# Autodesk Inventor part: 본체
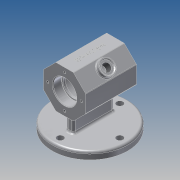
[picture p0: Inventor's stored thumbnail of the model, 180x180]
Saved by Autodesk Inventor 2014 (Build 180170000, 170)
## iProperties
Created: 2021-02
Part Number: 본체
Material: 알루미늄 6061
Document SubType Name: Modeling
Designer: kb542-20
Density: 2.71 g/cm^3
Appearance: 알루미늄 - 평지
Mass: 558.806 g
Surface Area: 509.67 cm^2
Volume: 206.202 cm^3
Author: kb542-20
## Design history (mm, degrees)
sketch "스케치1" dims "d0" = 58
  geometry: L1 (12.012, 29)-(29, 12.012); L2 (29, 12.012)-(29, -12.012); L3 (29, -12.012)-(12.012, -29); L4 (12.012, -29)-(-12.012, -29); L5 (-12.012, -29)-(-29, -12.012); L6 (-29, -12.012)-(-29, 12.012); L7 (-29, 12.012)-(-12.012, 29); L8 (-12.012, 29)-(12.012, 29); 5 further points
  constraints: 16 end point, 3 coincident, 1 horizontal, 1 midpoint, 1 vertical alignment, 19 other
extrude "돌출1" new body sketch "스케치1" stored distance "d1" = 70; taper "d2" = 0 deg
node "작업 평면1"
sketch "스케치3"
  geometry: C1 r 52 at (0, 0); C2 r 4.5 at (0, 41); C3 r 4.5 at (-41, 0); C4 r 4.5 at (0, -41); C5 r 4.5 at (41, 0); A1 r 41 centre (0, 0) between (0, 41) and (-41, 0); 1 further point
  constraints: 6 centre point, 4 point on circle, 3 equal radius, 2 coincident, 2 horizontal alignment, 2 vertical alignment
  dimensions: "d14" = 104 diameter of C1; "d15" = 82 diameter of A1; "d16" = 9 diameter of C2
extrude "돌출2" join sketch "스케치3" distance "d17" = 10; taper "d18" = 0 deg
sketch "스케치4"
  geometry: L1 (-5, 28)-(5, 28); L2 (5, 28)-(5, -28); L3 (5, -28)-(-5, -28); L4 (-5, -28)-(-5, 28); C1 r 52 at (0, 0) reference; 2 further points
  constraints: 8 end point, 2 midpoint, 2 parallel, 1 horizontal, 1 horizontal alignment, 1 perpendicular, 1 vertical alignment
  dimensions: "d19" = 56 distance of L1.end L2.end; "d20" = 10 distance of L1.start L1.end
extrude "돌출3" join sketch "스케치4" stored distance "d21" = 10; taper "d22" = 0 deg
sketch "스케치7"
  geometry: L1 (-35, 12.012)-(-35, -12.012) reference; L2 (-35, 0)-(0, 0); L3 (-35, 0)-(-35, 16); L4 (-35, 16)-(-23, 16); L5 (-23, 16)-(-23, 14); L6 (-23, 14)-(-20, 14); L7 (-20, 14)-(-20, 22); L8 (-20, 22)-(0, 22); L9 (0, 22)-(0, 0); L10 (35, 0)-(0, 0); L11 (35, 0)-(35, 16); L12 (35, 16)-(23, 16); L13 (23, 16)-(23, 14); L14 (23, 14)-(20, 14); L15 (20, 14)-(20, 22); L16 (20, 22)-(0, 22); 1 further point
  constraints: 30 end point, 7 symmetric about line, 5 parallel, 2 perpendicular, 1 midpoint
  dimensions: "d39" = 44 diameter of L16 L10; "d40" = 32 diameter of L4 L2; "d41" = 28 diameter of L6 L2; "d42" = 12 distance of L3.end L4.end; "d43" = 3 distance of L5.end L6.end
revolve "회전2" sketch "스케치7" stored, may be unused: angle "d44" = 90 deg
sketch "스케치8"
  geometry: L1 (-24.024, 70)-(0, 70) reference; L2 (-41.012, 0)-(-41.012, 70) reference; C1 r 10 at (-12.012, 35); 1 further point
  constraints: 1 centre point, 1 coincident
  dimensions: "d45" = 29 distance from line of L2 C1.centre (derived); "d46" = 35 distance from line of L1 point (-12.012, 35) (derived); "d47" = 20 diameter of C1
extrude "돌출5" join sketch "스케치8" distance "d48" = 5; taper "d49" = 0 deg
hole "구멍2" diameter "d52" = 10.917; stored, may be unused: countersink angle "d56" = 90 deg, drill point angle "d58" = 118 deg; dims "d50" = 10, "d51" = 10, "d53" = 6, "d54" = 16, "d55" = 2, "d57" = 8
sketch "스케치9"
  geometry: 2 further points
  constraints: 1 coincident, 1 other
feature "엠보싱2" sketch "스케치9" dims "d59" = 0.5, "d60" = 0
fillet "모깎기1" dims "d61" = 3, "d62" = 1
fillet "모깎기2" dims "d63" = 3, "d64" = 0.3
sketch "스케치10" dims "d65" = 46
  geometry: C1 r 16 at (0, 0) reference; 2 further points
  constraints: 2 vertical alignment, 1 coincident, 2 other
hole "구멍4" sketch "스케치10" at (0, 23) diameter "d73" = 3.242; stored, may be unused: countersink angle "d77" = 90 deg, drill point angle "d79" = 118 deg; dims "d74" = 8, "d75" = 16, "d76" = 2, "d78" = 10
chamfer "모따기1" distance "d83" = 1; stored, may be unused: second distance "d84" = 2, angle "d85" = 45 deg
node "솔리드1"
pattern_circular "원형 패턴1" dims angle "d81" = 360 deg
mirror "대칭1"
other parameters: "d13" = -62
